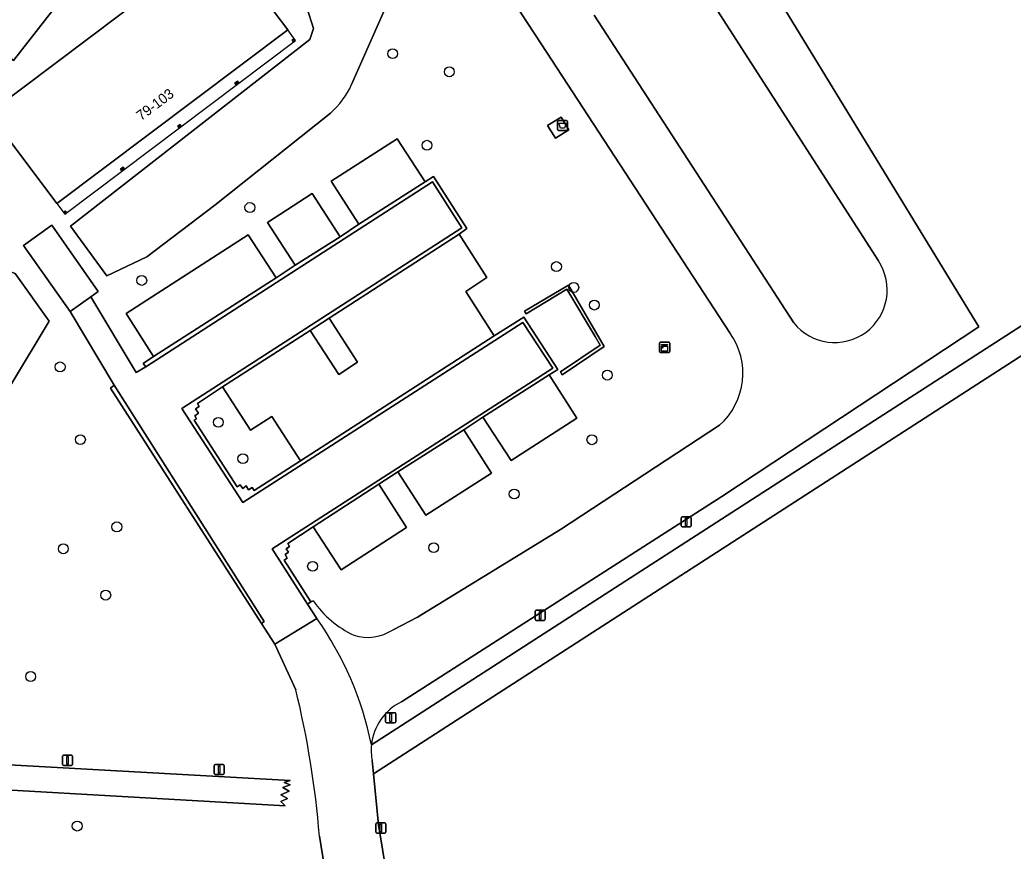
# Model space of a CAD drawing. Extents: x 159451 to 160664, y 388402 to 389723.
# Drawn here: x 159586.1 to 159684.1, y 389296.7 to 389378.7 of the extents above; entities that cross this region are included whole.
import ezdxf

# ---------------------------------------------------------------- set-up
doc = ezdxf.new("R2010")
doc.units = 0
for name, color, linetype in [('IMGEO_Afval_apart_plaats', 7, 'Continuous'), ('IMGEO_Boom', 7, 'Continuous'), ('IMGEO_Groenvoorziening', 7, 'Continuous'), ('IMGEO_Kast', 7, 'Continuous'), ('IMGEO_Lichtmast', 7, 'Continuous'), ('IMGEO_Meer_plas_ven_vijver', 7, 'Continuous'), ('IMGEO_Pand', 7, 'Continuous'), ('IMGEO_Pand_nummerreeks', 7, 'Continuous'), ('IMGEO_Pand_overbouw', 7, 'Continuous'), ('IMGEO_Parkeervlak_halfverhard', 7, 'Continuous'), ('IMGEO_Rijbaan_lokaal_gesloten', 7, 'Continuous'), ('IMGEO_Rijbaan_lokaal_halfverhard', 7, 'Continuous'), ('IMGEO_Rijbaan_lokaal_open', 7, 'Continuous'), ('IMGEO_Voetpad_gesloten', 7, 'Continuous'), ('IMGEO_Voetpad_halfverhard', 7, 'Continuous'), ('IMGEO_Voetpad_open', 7, 'Continuous')]:
    doc.layers.add(name, color=color, linetype=linetype)

msp = doc.modelspace()

# ---------------------------------------------------------------- linework, layer by layer
at = {"layer": 'IMGEO_Afval_apart_plaats'}
for p, q in [((159639.132, 389367.84), (159639.132, 389368.64)), ((159639.132, 389368.64), (159639.132, 389367.84)), ((159639.232, 389368.74), (159640.022, 389368.74)), ((159640.022, 389368.74), (159639.232, 389368.74)), ((159640.122, 389368.64), (159640.122, 389367.84)), ((159640.122, 389367.84), (159640.122, 389368.64)), ((159640.022, 389367.74), (159639.232, 389367.74)), ((159639.232, 389367.74), (159640.022, 389367.74))]:
    msp.add_line(p, q, dxfattribs=at)
msp.add_lwpolyline([(159639.275, 389368.454), (159639.979, 389368.454), (159639.83, 389367.984), (159639.424, 389367.984), (159639.275, 389368.454)], dxfattribs=at)
for centre, start, end in [((159639.232, 389368.64), 90, 180), ((159639.232, 389368.64), 90, 180), ((159640.022, 389368.64), 0, 90), ((159640.022, 389368.64), 360, 90), ((159639.232, 389367.84), 180, 270), ((159639.232, 389367.84), 180, 270), ((159640.022, 389367.84), 270, 0), ((159640.022, 389367.84), 270, 0)]:
    msp.add_arc(centre, 0.1, start, end, dxfattribs=at)
at = {"layer": 'IMGEO_Boom'}
for centre in [(159622.872, 389375.323), (159628.466, 389373.537), (159626.258, 389366.288), (159608.795, 389360.145), (159639.027, 389354.319), (159598.128, 389352.957), (159640.732, 389352.262), (159642.762, 389350.528), (159590.081, 389344.426), (159644.042, 389343.615), (159605.686, 389338.963), (159592.081, 389337.252), (159642.522, 389337.244), (159608.103, 389335.378), (159634.859, 389331.886), (159595.675, 389328.648), (159590.4, 389326.482), (159626.914, 389326.597), (159614.981, 389324.755), (159594.58, 389321.911), (159587.179, 389313.887), (159591.767, 389299.135)]:
    msp.add_circle(centre, 0.489, dxfattribs=at)
at = {"layer": 'IMGEO_Groenvoorziening'}
for points in [[(159585.487, 389374.644), (159576.692, 389381.52), (159598.547, 389409.538), (159607.34, 389402.676)], [(159589.76, 389360.534), (159583.054, 389369.444), (159605.812, 389386.575), (159612.526, 389377.663)], [(159613.074, 389376.537), (159612.978, 389376.665), (159613.122, 389376.773), (159613.218, 389376.645)], [(159607.668, 389372.469), (159607.412, 389372.277), (159607.316, 389372.405), (159607.571, 389372.597)], [(159639.481, 389369.047), (159640.249, 389367.807), (159638.924, 389366.987), (159638.141, 389368.251)], [(159602.028, 389368.226), (159601.772, 389368.033), (159601.676, 389368.161), (159601.931, 389368.354)], [(159596.392, 389363.985), (159596.138, 389363.795), (159596.04, 389363.921), (159596.295, 389364.113)], [(159590.563, 389359.6), (159590.467, 389359.728), (159590.595, 389359.824), (159590.691, 389359.696)], [(159639.579, 389343.638), (159639.439, 389343.93), (159643.347, 389346.561), (159642.836, 389347.42), (159640.049, 389352.104), (159636.055, 389349.651), (159635.89, 389349.928), (159640.225, 389352.484), (159643.746, 389346.447)], [(159606.105, 389342.451), (159603.628, 389340.828), (159603.806, 389340.526), (159603.444, 389340.289), (159603.744, 389339.863), (159603.362, 389339.61), (159603.525, 389339.305), (159603.313, 389339.166), (159607.536, 389332.597), (159607.85, 389332.804), (159608.09, 389332.442), (159608.431, 389332.683), (159608.644, 389332.299), (159609.021, 389332.541), (159609.225, 389332.233), (159613.795, 389335.171), (159610.949, 389339.542), (159608.859, 389338.202)]]:
    msp.add_lwpolyline(points, close=True, dxfattribs=at)
for points in [[(159656.126, 389347.781), (159637.529, 389376.31), (159634.211, 389381.399), (159652.747, 389394.079), (159655.465, 389389.687), (159680.667, 389348.366), (159655.336, 389331.641), (159623.745, 389311.39)], [(159591.093, 389358.32), (159614.718, 389376.735), (159615.079, 389377.795), (159614.436, 389379.787), (159613.104, 389383.71), (159606.954, 389392.211)], [(159670.775, 389354.886), (159651.844, 389384.351)], [(159622.613, 389380.94), (159618.83, 389372.291)], [(159642.738, 389379.108), (159662.418, 389348.774)], [(159620.782, 389307.136), (159687.881, 389350.402), (159687.335, 389351.245), (159691.299, 389353.81), (159685.228, 389357.891), (159688.494, 389362.8), (159691.829, 389360.53), (159694.921, 389365.09), (159696.591, 389367.56), (159701.858, 389370.867), (159707.944, 389373.119), (159708.3, 389372.238), (159711.804, 389362.903), (159620.983, 389304.296), (159621.487, 389299.27), (159623.828, 389284.864), (159629.586, 389251.444)], [(159616.729, 389369.443), (159605.352, 389360.378), (159598.626, 389355.276), (159594.681, 389353.399), (159591.093, 389358.32)], [(159613.321, 389312.584), (159611.239, 389317.075), (159609.928, 389319.12), (159595.057, 389342.34), (159595.399, 389342.61), (159591.074, 389349.897), (159586.47, 389356.404), (159589.258, 389358.394), (159593.822, 389351.872), (159593.097, 389351.323), (159597.59, 389343.867), (159598.522, 389344.436), (159598.283, 389344.767), (159599.303, 389345.442), (159596.586, 389349.686), (159608.624, 389357.451), (159611.385, 389353.224), (159613.267, 389354.447), (159610.538, 389358.687), (159614.923, 389361.525), (159617.692, 389357.266), (159619.55, 389358.499), (159616.804, 389362.759), (159623.307, 389366.937), (159626.095, 389362.677), (159626.895, 389363.203), (159630.203, 389358.068), (159629.417, 389357.527), (159632.147, 389353.245), (159630.08, 389351.88), (159632.897, 389347.493), (159635.81, 389349.344), (159639.147, 389344.171), (159638.292, 389343.642), (159641.019, 389339.354), (159634.544, 389335.207), (159631.782, 389339.457), (159629.889, 389338.224), (159632.622, 389333.939), (159626.158, 389329.812), (159623.399, 389334.07), (159621.512, 389332.869), (159624.252, 389328.571), (159617.799, 389324.41), (159615.031, 389328.65), (159612.521, 389327.021), (159612.713, 389326.719), (159612.36, 389326.469), (159612.602, 389326.158), (159612.271, 389325.917), (159612.466, 389325.57), (159612.173, 389325.361), (159614.816, 389321.244), (159615.036, 389321.364)], [(159579.281, 389347.357), (159581.666, 389351.038), (159582.45, 389352.959), (159583.776, 389354.373), (159585.651, 389353.634), (159589.012, 389348.926)], [(159589.012, 389348.926), (159585.291, 389342.745), (159583.718, 389341.973), (159580.859, 389343.226)], [(159622.915, 389318.505), (159625.315, 389319.747), (159639.439, 389328.387), (159655.095, 389338.67)], [(159569.711, 389306.038), (159612.776, 389303.614), (159612.166, 389303.421), (159612.757, 389303.197), (159612.044, 389302.952), (159612.655, 389302.565), (159611.86, 389302.198), (159612.513, 389301.851), (159611.84, 389301.566), (159612.27, 389301.143), (159568.631, 389303.617)], [(159618.859, 389278.354), (159615.655, 389298.149)]]:
    msp.add_lwpolyline(points, dxfattribs=at)
for centre, radius, start, end in [((159611.151, 389375.757), 8.425, 311.45918, 335.70764), ((159666.461, 389352.015), 5.182, 218.7153, 33.64541), ((159650.594, 389343.793), 6.82, 311.30208, 35.78568), ((159623.659, 389327.436), 10.547, 215.15277, 244.01351), ((159620.405, 389322.265), 4.521, 252.39623, 303.72326), ((159523.452, 389290.647), 92.508, 4.65164, 13.71772), ((159626.087, 389306.6), 5.332, 116.05771, 174.22625)]:
    msp.add_arc(centre, radius, start, end, dxfattribs=at)
at = {"layer": 'IMGEO_Kast'}
for p, q in [((159649.195, 389345.931), (159649.195, 389346.772)), ((159649.195, 389346.772), (159649.195, 389345.931)), ((159649.27, 389346.856), (159650.111, 389346.856)), ((159650.111, 389346.856), (159649.27, 389346.856)), ((159650.195, 389346.781), (159650.195, 389345.94)), ((159650.195, 389345.94), (159650.195, 389346.781)), ((159650.12, 389345.856), (159649.279, 389345.856)), ((159649.279, 389345.856), (159650.12, 389345.856))]:
    msp.add_line(p, q, dxfattribs=at)
for points in [[(159649.39, 389346.646), (159649.99, 389346.646), (159649.99, 389346.561), (159649.39, 389346.561), (159649.39, 389346.646)], [(159649.39, 389346.471), (159649.99, 389346.471), (159649.99, 389345.982), (159649.39, 389345.982), (159649.39, 389346.471)]]:
    msp.add_lwpolyline(points, dxfattribs=at)
msp.add_circle((159649.474, 389346.32), 0.0377, dxfattribs=at)
for centre, start, end in [((159649.273, 389346.778), 92.4484, 184.28452), ((159649.273, 389346.778), 92.4484, 184.28452), ((159650.117, 389346.778), 2.4484, 94.28452), ((159650.117, 389346.778), 2.4484, 94.28452), ((159649.273, 389345.934), 182.4484, 274.28452), ((159649.273, 389345.934), 182.4484, 274.28452), ((159650.117, 389345.934), 272.4484, 4.28452), ((159650.117, 389345.934), 272.4484, 4.28452)]:
    msp.add_arc(centre, 0.0779, start, end, dxfattribs=at)
at = {"layer": 'IMGEO_Lichtmast'}
for p, q in [((159651.323, 389328.741), (159651.323, 389329.541)), ((159651.323, 389329.541), (159651.323, 389328.741)), ((159651.423, 389329.641), (159652.213, 389329.641)), ((159652.213, 389329.641), (159651.423, 389329.641)), ((159652.313, 389329.541), (159652.313, 389328.741)), ((159652.313, 389328.741), (159652.313, 389329.541)), ((159652.213, 389328.641), (159651.423, 389328.641)), ((159651.423, 389328.641), (159652.213, 389328.641)), ((159636.923, 389319.527), (159636.923, 389320.327)), ((159636.923, 389320.327), (159636.923, 389319.527)), ((159637.023, 389320.427), (159637.813, 389320.427)), ((159637.813, 389320.427), (159637.023, 389320.427)), ((159637.913, 389320.327), (159637.913, 389319.527)), ((159637.913, 389319.527), (159637.913, 389320.327)), ((159637.813, 389319.427), (159637.023, 389319.427)), ((159637.023, 389319.427), (159637.813, 389319.427)), ((159622.181, 389309.418), (159622.181, 389310.218)), ((159622.181, 389310.218), (159622.181, 389309.418)), ((159622.281, 389310.318), (159623.071, 389310.318)), ((159623.071, 389310.318), (159622.281, 389310.318)), ((159623.171, 389310.218), (159623.171, 389309.418)), ((159623.171, 389309.418), (159623.171, 389310.218)), ((159623.071, 389309.318), (159622.281, 389309.318)), ((159622.281, 389309.318), (159623.071, 389309.318)), ((159590.311, 389305.219), (159590.311, 389306.019)), ((159590.311, 389306.019), (159590.311, 389305.219)), ((159590.411, 389306.119), (159591.201, 389306.119)), ((159591.201, 389306.119), (159590.411, 389306.119)), ((159591.301, 389306.019), (159591.301, 389305.219)), ((159591.301, 389305.219), (159591.301, 389306.019)), ((159591.201, 389305.119), (159590.411, 389305.119)), ((159590.411, 389305.119), (159591.201, 389305.119)), ((159605.277, 389304.311), (159605.277, 389305.111)), ((159605.277, 389305.111), (159605.277, 389304.311)), ((159605.377, 389305.211), (159606.167, 389305.211)), ((159606.167, 389305.211), (159605.377, 389305.211)), ((159606.267, 389305.111), (159606.267, 389304.311)), ((159606.267, 389304.311), (159606.267, 389305.111)), ((159606.167, 389304.211), (159605.377, 389304.211)), ((159605.377, 389304.211), (159606.167, 389304.211)), ((159621.315, 389299.446), (159622.105, 389299.446)), ((159622.105, 389299.446), (159621.315, 389299.446)), ((159621.215, 389298.546), (159621.215, 389299.346)), ((159621.215, 389299.346), (159621.215, 389298.546)), ((159622.105, 389298.446), (159621.315, 389298.446)), ((159621.315, 389298.446), (159622.105, 389298.446)), ((159622.205, 389299.346), (159622.205, 389298.546)), ((159622.205, 389298.546), (159622.205, 389299.346))]:
    msp.add_line(p, q, dxfattribs=at)
for points in [[(159651.743, 389329.516), (159651.893, 389329.516), (159651.893, 389328.766), (159651.743, 389328.766), (159651.743, 389329.516)], [(159637.343, 389320.302), (159637.493, 389320.302), (159637.493, 389319.552), (159637.343, 389319.552), (159637.343, 389320.302)], [(159622.601, 389310.193), (159622.751, 389310.193), (159622.751, 389309.443), (159622.601, 389309.443), (159622.601, 389310.193)], [(159590.731, 389305.994), (159590.881, 389305.994), (159590.881, 389305.244), (159590.731, 389305.244), (159590.731, 389305.994)], [(159605.697, 389305.086), (159605.847, 389305.086), (159605.847, 389304.336), (159605.697, 389304.336), (159605.697, 389305.086)], [(159621.635, 389299.321), (159621.785, 389299.321), (159621.785, 389298.571), (159621.635, 389298.571), (159621.635, 389299.321)]]:
    msp.add_lwpolyline(points, dxfattribs=at)
for centre, start, end in [((159651.423, 389329.541), 90, 180), ((159651.423, 389329.541), 90, 180), ((159651.423, 389328.741), 180, 270), ((159651.423, 389328.741), 180, 270), ((159652.213, 389329.541), 0, 90), ((159652.213, 389329.541), 360, 90), ((159652.213, 389328.741), 270, 0), ((159652.213, 389328.741), 270, 0), ((159637.023, 389320.327), 90, 180), ((159637.023, 389320.327), 90, 180), ((159637.813, 389320.327), 0, 90), ((159637.813, 389320.327), 360, 90), ((159637.023, 389319.527), 180, 270), ((159637.023, 389319.527), 180, 270), ((159637.813, 389319.527), 270, 0), ((159637.813, 389319.527), 270, 0), ((159622.281, 389310.218), 90, 180), ((159622.281, 389310.218), 90, 180), ((159623.071, 389310.218), 0, 90), ((159623.071, 389310.218), 360, 90), ((159622.281, 389309.418), 180, 270), ((159622.281, 389309.418), 180, 270), ((159623.071, 389309.418), 270, 0), ((159623.071, 389309.418), 270, 0), ((159590.411, 389306.019), 90, 180), ((159590.411, 389306.019), 90, 180), ((159591.201, 389306.019), 0, 90), ((159591.201, 389306.019), 360, 90), ((159590.411, 389305.219), 180, 270), ((159590.411, 389305.219), 180, 270), ((159591.201, 389305.219), 270, 0), ((159591.201, 389305.219), 270, 0), ((159605.377, 389305.111), 90, 180), ((159605.377, 389305.111), 90, 180), ((159605.377, 389304.311), 180, 270), ((159605.377, 389304.311), 180, 270), ((159606.167, 389305.111), 0, 90), ((159606.167, 389305.111), 360, 90), ((159606.167, 389304.311), 270, 0), ((159606.167, 389304.311), 270, 0), ((159621.315, 389299.346), 90, 180), ((159621.315, 389299.346), 90, 180), ((159622.105, 389299.346), 0, 90), ((159622.105, 389299.346), 360, 90), ((159621.315, 389298.546), 180, 270), ((159621.315, 389298.546), 180, 270), ((159622.105, 389298.546), 270, 0), ((159622.105, 389298.546), 270, 0)]:
    msp.add_arc(centre, 0.1, start, end, dxfattribs=at)
at = {"layer": 'IMGEO_Meer_plas_ven_vijver'}
for points in [[(159606.954, 389392.211), (159613.104, 389383.71), (159614.436, 389379.787), (159615.079, 389377.795), (159614.718, 389376.735), (159591.093, 389358.32)], [(159618.83, 389372.291), (159622.613, 389380.94)], [(159591.093, 389358.32), (159594.681, 389353.399), (159598.626, 389355.276), (159605.352, 389360.378), (159616.729, 389369.443)], [(159589.012, 389348.926), (159585.651, 389353.634), (159583.776, 389354.373), (159582.45, 389352.959), (159581.666, 389351.038), (159579.281, 389347.357)], [(159580.859, 389343.226), (159583.718, 389341.973), (159585.291, 389342.745), (159589.012, 389348.926)]]:
    msp.add_lwpolyline(points, dxfattribs=at)
msp.add_arc((159611.151, 389375.757), 8.425, 311.45918, 335.70764, dxfattribs=at)
at = {"layer": 'IMGEO_Pand'}
for points in [[(159607.34, 389402.676), (159598.547, 389409.538), (159576.692, 389381.52), (159585.487, 389374.644)], [(159612.526, 389377.663), (159605.812, 389386.575), (159583.054, 389369.444), (159589.76, 389360.534)], [(159613.122, 389376.773), (159612.978, 389376.665), (159613.074, 389376.537), (159613.218, 389376.645)], [(159607.668, 389372.469), (159607.571, 389372.597), (159607.316, 389372.405), (159607.412, 389372.277)], [(159602.028, 389368.226), (159601.931, 389368.354), (159601.676, 389368.161), (159601.772, 389368.033)], [(159596.392, 389363.985), (159596.295, 389364.113), (159596.04, 389363.921), (159596.138, 389363.795)], [(159590.595, 389359.824), (159590.467, 389359.728), (159590.563, 389359.6), (159590.691, 389359.696)]]:
    msp.add_lwpolyline(points, close=True, dxfattribs=at)
at = {"layer": 'IMGEO_Pand_overbouw'}
msp.add_lwpolyline([(159613.305, 389376.629), (159612.526, 389377.663), (159589.76, 389360.534), (159590.538, 389359.501)], close=True, dxfattribs=at)
at = {"layer": 'IMGEO_Parkeervlak_halfverhard'}
for points in [[(159626.095, 389362.677), (159623.307, 389366.937), (159616.804, 389362.759), (159619.55, 389358.499)], [(159613.267, 389354.447), (159617.692, 389357.266), (159614.923, 389361.525), (159610.538, 389358.687)], [(159611.385, 389353.224), (159608.624, 389357.451), (159596.586, 389349.686), (159599.303, 389345.442)], [(159629.417, 389357.527), (159616.602, 389349.25), (159619.409, 389344.88), (159617.552, 389343.678), (159614.728, 389348.033), (159606.105, 389342.451), (159608.859, 389338.202), (159610.949, 389339.542), (159613.795, 389335.171), (159632.897, 389347.493), (159630.08, 389351.88), (159632.147, 389353.245)], [(159638.292, 389343.642), (159631.782, 389339.457), (159634.544, 389335.207), (159641.019, 389339.354)], [(159629.889, 389338.224), (159623.399, 389334.07), (159626.158, 389329.812), (159632.622, 389333.939)], [(159621.512, 389332.869), (159615.031, 389328.65), (159617.799, 389324.41), (159624.252, 389328.571)]]:
    msp.add_lwpolyline(points, close=True, dxfattribs=at)
at = {"layer": 'IMGEO_Rijbaan_lokaal_gesloten'}
for points in [[(159623.745, 389311.39), (159655.336, 389331.641), (159680.667, 389348.366), (159655.465, 389389.687), (159652.747, 389394.079), (159634.211, 389381.399), (159637.529, 389376.31)], [(159651.844, 389384.351), (159670.775, 389354.886)], [(159662.418, 389348.774), (159642.738, 389379.108)], [(159637.529, 389376.31), (159656.126, 389347.781)], [(159655.095, 389338.67), (159639.439, 389328.387), (159625.315, 389319.747), (159622.915, 389318.505)], [(159615.036, 389321.364), (159614.816, 389321.244), (159614.479, 389321.018), (159615.389, 389319.623)], [(159615.389, 389319.623), (159611.239, 389317.075), (159613.321, 389312.584)], [(159612.776, 389303.614), (159569.711, 389306.038)], [(159620.983, 389304.296), (159620.853, 389305.586)], [(159629.586, 389251.444), (159623.828, 389284.864), (159621.487, 389299.27), (159620.983, 389304.296)], [(159568.631, 389303.617), (159612.27, 389301.143), (159611.84, 389301.566), (159612.513, 389301.851), (159611.86, 389302.198), (159612.655, 389302.565), (159612.044, 389302.952), (159612.757, 389303.197), (159612.166, 389303.421), (159612.776, 389303.614)], [(159615.655, 389298.149), (159618.859, 389278.354)]]:
    msp.add_lwpolyline(points, dxfattribs=at)
for points in [[(159629.682, 389358.16), (159626.787, 389362.691), (159598.522, 389344.436), (159597.59, 389343.867), (159593.097, 389351.323), (159591.074, 389349.897), (159595.399, 389342.61), (159610.199, 389319.324), (159609.928, 389319.12), (159611.239, 389317.075), (159615.389, 389319.623), (159614.479, 389321.018), (159610.982, 389326.488), (159638.659, 389344.315), (159635.706, 389348.811), (159608.085, 389331.051), (159602.087, 389340.314)], [(159591.074, 389349.897), (159593.097, 389351.323), (159593.822, 389351.872), (159589.258, 389358.394), (159586.47, 389356.404)]]:
    msp.add_lwpolyline(points, close=True, dxfattribs=at)
for centre, radius, start, end in [((159666.461, 389352.015), 5.182, 218.7153, 33.64541), ((159650.594, 389343.793), 6.82, 311.30208, 35.78568), ((159623.659, 389327.436), 10.547, 215.15277, 244.01351), ((159588.41, 389300.563), 33.033, 11.47784, 35.24014), ((159588.41, 389300.563), 33.033, 11.47784, 35.24014), ((159620.405, 389322.265), 4.521, 252.39623, 303.72326), ((159523.452, 389290.647), 92.508, 4.65164, 13.71772), ((159626.087, 389306.6), 5.332, 116.05771, 174.22625), ((159626.107, 389306.603), 5.352, 174.28729, 190.95808)]:
    msp.add_arc(centre, radius, start, end, dxfattribs=at)
at = {"layer": 'IMGEO_Rijbaan_lokaal_halfverhard'}
for points in [[(159711.804, 389362.903), (159708.3, 389372.238), (159707.944, 389373.119), (159701.858, 389370.867), (159696.591, 389367.56), (159694.921, 389365.09), (159691.829, 389360.53), (159688.494, 389362.8), (159685.228, 389357.891), (159691.299, 389353.81), (159687.335, 389351.245), (159687.881, 389350.402), (159620.782, 389307.136)], [(159620.853, 389305.586), (159620.983, 389304.296), (159711.804, 389362.903)]]:
    msp.add_lwpolyline(points, dxfattribs=at)
msp.add_lwpolyline([(159595.399, 389342.61), (159595.057, 389342.34), (159609.928, 389319.12), (159610.199, 389319.324)], close=True, dxfattribs=at)
msp.add_arc((159626.107, 389306.603), 5.352, 174.28729, 190.95808, dxfattribs=at)
at = {"layer": 'IMGEO_Rijbaan_lokaal_open'}
msp.add_lwpolyline([(159629.682, 389358.16), (159602.087, 389340.314), (159608.085, 389331.051), (159635.706, 389348.811), (159638.659, 389344.315), (159610.982, 389326.488), (159614.479, 389321.018), (159614.816, 389321.244), (159612.173, 389325.361), (159612.466, 389325.57), (159612.271, 389325.917), (159612.602, 389326.158), (159612.36, 389326.469), (159612.713, 389326.719), (159612.521, 389327.021), (159615.031, 389328.65), (159621.512, 389332.869), (159623.399, 389334.07), (159629.889, 389338.224), (159631.782, 389339.457), (159638.292, 389343.642), (159639.147, 389344.171), (159635.81, 389349.344), (159632.897, 389347.493), (159613.795, 389335.171), (159609.225, 389332.233), (159609.021, 389332.541), (159608.644, 389332.299), (159608.431, 389332.683), (159608.09, 389332.442), (159607.85, 389332.804), (159607.536, 389332.597), (159603.313, 389339.166), (159603.525, 389339.305), (159603.362, 389339.61), (159603.744, 389339.863), (159603.444, 389340.289), (159603.806, 389340.526), (159603.628, 389340.828), (159606.105, 389342.451), (159614.728, 389348.033), (159616.602, 389349.25), (159629.417, 389357.527), (159630.203, 389358.068), (159626.895, 389363.203), (159626.095, 389362.677), (159619.55, 389358.499), (159617.692, 389357.266), (159613.267, 389354.447), (159611.385, 389353.224), (159599.303, 389345.442), (159598.283, 389344.767), (159598.522, 389344.436), (159626.787, 389362.691)], close=True, dxfattribs=at)
at = {"layer": 'IMGEO_Voetpad_gesloten'}
msp.add_lwpolyline([(159639.481, 389369.047), (159638.141, 389368.251), (159638.924, 389366.987), (159640.249, 389367.807)], close=True, dxfattribs=at)
at = {"layer": 'IMGEO_Voetpad_halfverhard'}
msp.add_lwpolyline([(159616.602, 389349.25), (159614.728, 389348.033), (159617.552, 389343.678), (159619.409, 389344.88)], close=True, dxfattribs=at)
at = {"layer": 'IMGEO_Voetpad_open'}
msp.add_lwpolyline([(159639.579, 389343.638), (159643.746, 389346.447), (159640.225, 389352.484), (159635.89, 389349.928), (159636.055, 389349.651), (159640.049, 389352.104), (159642.836, 389347.42), (159643.347, 389346.561), (159639.439, 389343.93)], close=True, dxfattribs=at)

# ---------------------------------------------------------------- texts
at = {"layer": 'IMGEO_Pand_nummerreeks'}
msp.add_text('79-103', height=1, rotation=36.95578, dxfattribs=at).set_placement((159598.074, 389368.666))

doc.saveas('drawing.dxf')
